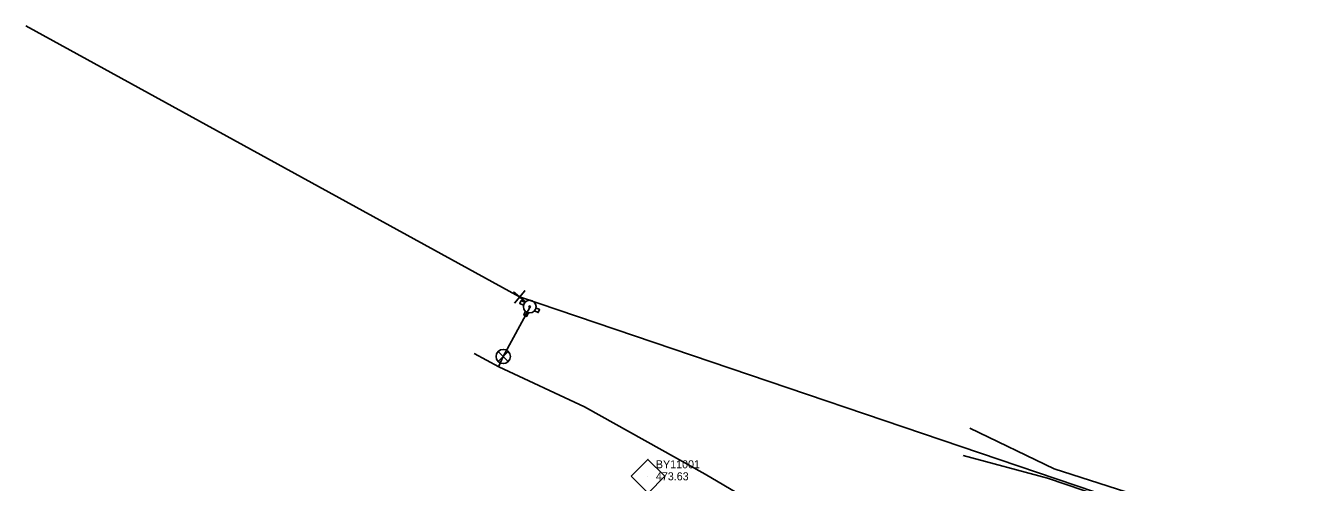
# Model space of a CAD drawing. Extents: x 2074109 to 2077820, y 741079 to 746031.
# Drawn here: x 2074521.3 to 2074923.4, y 743853.8 to 743996.5 of the extents above; entities that cross this region are included whole.
import ezdxf

# ---------------------------------------------------------------- set-up
doc = ezdxf.new("R2010")
doc.units = 0
for name, color, linetype in [('CTL Secondary Horizontal and Vertical CELL', 7, 'Continuous'), ('CTL Secondary Horizontal and Vertical Cogo Elevation', 7, 'Continuous'), ('CTL Secondary Horizontal and Vertical Cogo Number', 7, 'Continuous'), ('Exist Other Culture Fence Line', 7, 'Continuous'), ('Exist Property Corner CELL', 7, 'Continuous'), ('Exist Right of Way Line', 7, 'Continuous'), ('Exist Utilities Water Fire Hydrant CELL', 7, 'Continuous'), ('Exist Utilities Water UG Line SUE LOS B', 7, 'Continuous'), ('Exist Utilities Water Valve CELL', 7, 'Continuous'), ('Exist Vegetation Hedge Row', 7, 'Continuous')]:
    doc.layers.add(name, color=color, linetype=linetype)

msp = doc.modelspace()

# ---------------------------------------------------------------- linework, layer by layer
at = {"layer": 'CTL Secondary Horizontal and Vertical CELL'}
msp.add_line((2074715.62, 743855.67), (2074715.62, 743855.67), dxfattribs=at)
msp.add_lwpolyline([(2074710.41, 743855.69), (2074715.65, 743860.93), (2074720.9, 743855.68), (2074715.66, 743850.44)], close=True, dxfattribs=at)
at = {"layer": 'Exist Other Culture Fence Line'}
msp.add_lwpolyline([(2074814.07, 743862.14), (2074840.43, 743855.05), (2074902.69, 743833.95)], dxfattribs=at)
at = {"layer": 'Exist Property Corner CELL'}
msp.add_line((2074675.55, 743911.73), (2074675.55, 743911.73), dxfattribs=at)
msp.add_lwpolyline([(2074673.62, 743913.33), (2074677.47, 743910.13), (2074675.55, 743911.73), (2074677.15, 743913.65), (2074673.95, 743909.8)], dxfattribs=at)
at = {"layer": 'Exist Right of Way Line'}
for p, q in [((2074521.34, 743996.49), (2074675.55, 743911.73)), ((2074675.55, 743911.73), (2074938.55, 743822.55))]:
    msp.add_line(p, q, dxfattribs=at)
at = {"layer": 'Exist Utilities Water Fire Hydrant CELL'}
msp.add_line((2074678.73, 743908.72), (2074678.73, 743908.72), dxfattribs=at)
for points in [[(2074676.79, 743909.11), (2074675.63, 743909.68), (2074676.09, 743910.6), (2074677.26, 743910.01)], [(2074680.21, 743907.41), (2074681.37, 743906.83), (2074681.82, 743907.75), (2074680.65, 743908.33)], [(2074677.42, 743907.23), (2074676.84, 743906.08), (2074677.76, 743905.62), (2074678.34, 743906.77)]]:
    msp.add_lwpolyline(points, dxfattribs=at)
for radius in [1.98, 0.243]:
    msp.add_circle((2074678.73, 743908.72), radius, dxfattribs=at)
at = {"layer": 'Exist Utilities Water UG Line SUE LOS B'}
for points in [[(2074678.82, 743908.59), (2074670.47, 743893.12), (2074669, 743889.87)], [(2074661.41, 743894.07), (2074669.03, 743889.86), (2074695.78, 743877.33), (2074733.5, 743856.32), (2074766.19, 743837.03), (2074806.52, 743814.12), (2074828.36, 743801.4), (2074869.77, 743778.77), (2075138.71, 743653.82), (2075174.59, 743638.37), (2075261.38, 743603.22), (2075296.53, 743589.33), (2075345.56, 743568.62), (2075373.37, 743552.36), (2075399.34, 743536.02), (2075447.19, 743500.05), (2075713.36, 743360.43), (2075744.72, 743342.27), (2075764.85, 743330.17), (2075782.75, 743317.7), (2075822.78, 743289.56)]]:
    msp.add_lwpolyline(points, dxfattribs=at)
at = {"layer": 'Exist Utilities Water Valve CELL'}
msp.add_lwpolyline([(2074672.01, 743894.68), (2074668.86, 743891.53), (2074670.44, 743893.11), (2074672.01, 743891.53), (2074668.86, 743894.68)], dxfattribs=at)
msp.add_circle((2074670.44, 743893.11), 2.23, dxfattribs=at)
at = {"layer": 'Exist Vegetation Hedge Row'}
msp.add_lwpolyline([(2074816.16, 743870.76), (2074842.47, 743857.99), (2074920.95, 743832.84)], dxfattribs=at)

# ---------------------------------------------------------------- texts
at = {"layer": 'CTL Secondary Horizontal and Vertical Cogo Elevation'}
msp.add_text('473.63', height=2.5, dxfattribs=at).set_placement((2074718.12, 743854.42))
at = {"layer": 'CTL Secondary Horizontal and Vertical Cogo Number'}
msp.add_text('BY11001', height=2.5, dxfattribs=at).set_placement((2074718.12, 743858.17))

doc.saveas('drawing.dxf')
